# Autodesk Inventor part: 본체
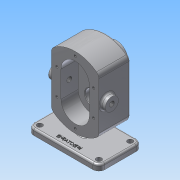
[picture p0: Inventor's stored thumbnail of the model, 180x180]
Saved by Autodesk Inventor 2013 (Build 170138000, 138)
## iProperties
Created: 2019-03
Part Number: 본체
Material: 알루미늄 6061
Document SubType Name: Modeling
Designer: Administrator
Mass: 1191.56 g
Surface Area: 719.273 cm^2
Volume: 439.69 cm^3
Density: 2.71 g/cm^3
Author: Administrator
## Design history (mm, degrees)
sketch "스케치1"
  geometry: L1 (-40, -60)-(40, -60); L2 (40, -44.721)-(40, 44.721); L3 (40, 60)-(-40, 60); L4 (-40, 60)-(-40, -60); L5 (-40, -60)-(40, 60); L6 (40, -60)-(-40, 60); A1 r 60 centre (0, 0) between (40, 44.721) and (-40, 44.721); A2 r 60 centre (0, 0) between (-40, -44.721) and (40, -44.721); 3 further points
  constraints: 12 end point, 4 midpoint, 4 point on circle, 2 centre point, 2 coincident, 2 parallel, 2 point on line, 2 tangent, 1 horizontal, 1 perpendicular
  dimensions: "d1" = 80 distance of L3.end L3.start; "d3" = 60 radius of A1; "d4" = 60 radius of A2; "d5" = 89.44272 distance of L2.start L2.end; "d6" = 80 distance between parallel lines of L4 L2; "d7" = 40 distance from line of L2 point (0, 0)
extrude "돌출1" new body sketch "스케치1" distance "d8" = 53; taper "d9" = 0 deg
fillet "모깎기1" dims "d10" = 10
sketch "스케치2"
  geometry: L1 (-40, 40)-(-40, -40) reference; L2 (0, 0)-(0, 22); L3 (0, 0)-(0, -22); L4 (-24, 22)-(-24, -22); L5 (24, 22)-(24, -22); A1 r 60 centre (0, 0) between (36, 48) and (-36, 48) reference; A2 r 24 centre (0, 22) between (24, 22) and (9.592, 0); A3 r 24 centre (0, -22) between (-24, -22) and (-9.592, 0)
  constraints: 8 end point, 8 point on circle, 3 parallel, 2 centre point, 2 coincident, 2 tangent, 1 collinear
  dimensions: "d11" = 22 distance of L2.start L2.end; "d12" = 48 diameter of A2; "d13" = 22 distance of L2.start L3.end; "d14" = 48 diameter of A3
extrude "돌출2" cut sketch "스케치2" distance "d15" = 29; taper "d16" = 0 deg
sketch "스케치3"
  geometry: C1 r 12.5 at (0, -22); C2 r 12.5 at (0, 22); A1 r 24 centre (0, -22) between (-24, -22) and (24, -22) reference; A2 r 24 centre (0, 22) between (24, 22) and (-24, 22) reference; 1 further point
  constraints: 2 centre point, 2 coincident
  dimensions: "d17" = 25 diameter of C1; "d18" = 25 diameter of C2
extrude "돌출3" cut sketch "스케치3" distance "d19" = 15; taper "d20" = 0 deg
sketch "스케치4"
  geometry: L1 (-40, -40)-(-40, 40) reference; L2 (0, 0)-(0, 22); C1 r 19 at (0, 22); A1 r 60 centre (0, 0) between (-36, -48) and (36, -48) reference
  constraints: 2 end point, 1 centre point, 1 coincident, 1 parallel
  dimensions: "d21" = 22 distance of L2.start L2.end; "d22" = 38 diameter of C1
extrude "돌출4" join sketch "스케치4" distance "d23" = 17; taper "d24" = 0 deg
sketch "스케치5"
  geometry: C1 r 19 at (0, 0) reference; 2 further points
  constraints: 1 coincident
hole "구멍1" sketch "스케치5" at (0, 0) diameter "d25" = 17; stored, may be unused: countersink angle "d29" = 90 deg, drill point angle "d31" = 118 deg; dims "d26" = 6, "d27" = 28, "d28" = 7.3, "d30" = 8
sketch "스케치6"
  geometry: L1 (46, 24)-(46, 53) reference; L2 (46, 53)-(60, 53) reference; L3 (60, 53)-(60, 0) reference; L4 (60, 0)-(41, 0) reference; L5 (41, 0)-(41, -17) reference; L6 (41, -17)-(36, -17) reference; L7 (36, -17)-(36, -9.7) reference; L8 (36, -9.7)-(30.5, -9.7) reference; L9 (30.5, -9.7)-(30.5, 9) reference; L10 (30.5, 9)-(34.5, 9) reference; L11 (34.5, 9)-(34.5, 24) reference; L12 (34.5, 24)-(46, 24) reference; L13 (-46, 53)-(-46, 24) reference; L14 (-46, 24)-(-34.5, 24) reference; L15 (-34.5, 24)-(-34.5, 9) reference; L16 (-34.5, 9)-(-9.5, 9) reference; L17 (-9.5, 9)-(-9.5, 24) reference; L18 (-9.5, 24)-(9.5, 24) reference; L19 (9.5, 24)-(9.5, 9) reference; L20 (9.5, 9)-(13.5, 9) reference; L21 (13.5, 9)-(13.5, -9.7) reference; L22 (13.5, -9.7)-(8, -9.7) reference; L23 (8, -9.7)-(8, -17) reference; L24 (8, -17)-(3, -17) reference; L25 (3, -17)-(3, 0) reference; L26 (3, 0)-(-60, 0) reference; L27 (-60, 0)-(-60, 53) reference; L28 (-60, 53)-(-46, 53) reference; L29 (36, -9.7)-(36, -17) reference; L30 (3, -17)-(41, -17) reference; L31 (8, -9.7)-(8, -17) reference; L32 (36, -17)-(36, -16.3); L33 (36, -16.3)-(36.404, -17); L34 (41, 0)-(3, 0) reference; L35 (22, 0)-(22, -17); L36 (36, -16.3)-(22, -16.3); L37 (22, -17)-(36.404, -17); 1 further point
  constraints: 10 end point, 3 point on line, 2 midpoint, 1 parallel, 1 perpendicular
  dimensions: "d32" = 0.7 distance of L29.end L32.end; "d33" = 30 deg angle of L32 L33
revolve "회전1" sketch "스케치6" stored, may be unused: angle "d34" = 90 deg
fillet "모깎기2" dims "d35" = 0.5
chamfer "모따기1" distance "d36" = 1; stored, may be unused: second distance "d37" = 2, angle "d38" = 45 deg
sketch "스케치7"
  geometry: L1 (-53, 0)-(-53, 80) reference; C1 r 11 at (-39, 40); 1 further point
  constraints: 1 centre point
  dimensions: "d40" = 22 diameter of C1; "d86" = 14 distance from line of C1.centre L1
extrude "돌출5" join sketch "스케치7" distance "d41" = 8; taper "d42" = 0 deg
sketch "스케치8"
  geometry: C1 r 11 at (0, 0) reference; 2 further points
  constraints: 1 coincident
hole "구멍2" sketch "스케치8" at (0, 0) diameter "d43" = 8.376; stored, may be unused: countersink angle "d47" = 90 deg, drill point angle "d49" = 118 deg; dims "d44" = 6, "d45" = 28, "d46" = 7.3, "d48" = 8
fillet "모깎기3" dims "d50" = 3
sketch "스케치9"
  geometry: A1 r 24 centre (0, 22) between (24, 22) and (-24, 22) reference; A2 r 24 centre (0, -22) between (-24, -22) and (24, -22) reference; A3 r 60 centre (0, 0) between (-36, -48) and (36, -48) reference; A4 r 60 centre (0, 0) between (36, 48) and (-36, 48) reference; A5 r 31 centre (0, 22) between (0, 53) and (-31, 22); A6 r 31 centre (0, -22) between (0, -53) and (31, -22); 2 further points
  constraints: 6 point on circle, 3 horizontal alignment, 3 vertical alignment, 2 centre point, 2 coincident
  dimensions: "d51" = 62 diameter of A5; "d52" = 62 diameter of A6; "d53" = 62 distance of A6.end point (-31, -22)
hole "구멍3" sketch "스케치9" at (0, 53), (-31, 22), (31, 22), (0, -53), (31, -22), (-31, -22) diameter "d54" = 4.134; stored, may be unused: countersink angle "d58" = 90 deg, drill point angle "d60" = 118 deg; dims "d55" = 10, "d56" = 28, "d57" = 7.3, "d59" = 12
node "작업 평면1"
sketch "스케치10"
  geometry: L1 (36, 53)-(-36, 53) reference; L2 (-60, 0)-(60, 0); L3 (60, 0)-(60, 73); L4 (60, 73)-(-60, 73); L5 (-60, 73)-(-60, 0); L6 (40, 0)-(40, 53) reference; L7 (-40, 53)-(-40, 0) reference; 2 further points
  constraints: 8 end point, 2 parallel, 1 coincident, 1 horizontal, 1 midpoint, 1 perpendicular
  dimensions: "d62" = 120 distance of L4.end L3.end; "d63" = 73 distance of L3.end L2.end
extrude "돌출6" join sketch "스케치10" distance "d64" = 10; taper "d65" = 0 deg
fillet "모깎기4" dims "d66" = 10
sketch "스케치11"
  geometry: A1 r 10 centre (-50, -10) between (-50, 0) and (-60, -10) reference; A2 r 10 centre (-50, -63) between (-60, -63) and (-50, -73) reference; A3 r 10 centre (50, -63) between (50, -73) and (60, -63) reference; A4 r 10 centre (50, -10) between (60, -10) and (50, 0) reference; 5 further points
  constraints: 4 coincident
hole "구멍4" sketch "스케치11" at (-50, -63), (-50, -10), (50, -10), (50, -63) diameter "d67" = 9; stored, may be unused: countersink angle "d71" = 90 deg, drill point angle "d73" = 118 deg; dims "d68" = 10, "d69" = 28, "d70" = 7.3, "d72" = 12
sketch "스케치12"
  geometry: L1 (-78, 0)-(-78, 73) reference; L2 (-78, 73)-(-68, 73) reference; L3 (-68, 73)-(-68, 0) reference; L4 (-68, 0)-(-78, 0) reference; L5 (3, -17)-(3, 0) reference; L6 (3, 0)-(-60, 0) reference; L7 (-60, 0)-(-60, 53) reference; L8 (-60, 53)-(-55.067, 53) reference; L9 (-55.067, 53)-(-55.067, 41) reference; L10 (-55.067, 41)-(-53, 39.758) reference; L11 (-53, 39.758)-(-50.933, 41) reference; L12 (-50.933, 41)-(-50.933, 53) reference; L13 (-50.933, 53)-(-46, 53) reference; L14 (-46, 53)-(-46, 24) reference; L15 (-46, 24)-(-35.5, 24) reference; L16 (-35.5, 24)-(-34.5, 23) reference; L17 (-34.5, 23)-(-34.5, 9) reference; L18 (-34.5, 9)-(-9.5, 9) reference; L19 (-9.5, 9)-(-9.5, 23) reference; L20 (-9.5, 23)-(-8.5, 24) reference; L21 (-8.5, 24)-(8.5, 24) reference; L22 (8.5, 24)-(9.5, 23) reference; L23 (9.5, 23)-(9.5, 9) reference; L24 (9.5, 9)-(13.5, 9) reference; L25 (13.5, 9)-(13.5, -9.7) reference; L26 (13.5, -9.7)-(8.5, -9.7) reference; L27 (8, -10.2)-(8, -16.3) reference; L28 (8, -16.3)-(7.596, -17) reference; L29 (7.596, -17)-(3, -17) reference; L30 (41, 0)-(41, -17) reference; L31 (41, -17)-(36.404, -17) reference; L32 (36.404, -17)-(36, -16.3) reference; L33 (36, -16.3)-(36, -10.2) reference; L34 (35.5, -9.7)-(30.5, -9.7) reference; L35 (30.5, -9.7)-(30.5, 9) reference; L36 (30.5, 9)-(34.5, 9) reference; L37 (34.5, 9)-(34.5, 23) reference; L38 (34.5, 23)-(35.5, 24) reference; L39 (35.5, 24)-(46, 24) reference; L40 (46, 24)-(46, 53) reference; L41 (46, 53)-(50.933, 53) reference; L42 (50.933, 53)-(50.933, 41) reference; L43 (50.933, 41)-(53, 39.758) reference; L44 (53, 39.758)-(55.067, 41) reference; L45 (55.067, 41)-(55.067, 53) reference; L46 (55.067, 53)-(60, 53) reference; L47 (60, 53)-(60, 0) reference; L48 (60, 0)-(41, 0) reference; L49 (-68, 0)-(-56.692, 0); L50 (-56.692, 0)-(-56.692, 43); L51 (-56.692, 43)-(-68, 43); L52 (-68, 43)-(-68, 0); A1 r 0.5 centre (8.5, -10.2) between (8.5, -9.7) and (8, -10.2) reference; A2 r 0.5 centre (35.5, -10.2) between (36, -10.2) and (35.5, -9.7) reference; 1 further point
  constraints: 8 end point, 2 parallel, 1 horizontal, 1 perpendicular
  dimensions: "d74" = 43 distance of L50.end L49.end
extrude "돌출7" join sketch "스케치12" stored distance "d75" = 12; taper "d76" = 0 deg
fillet "모깎기5" dims "d77" = 3
fillet "모깎기6" dims "d78" = 3
fillet "모깎기7" dims "d79" = 3
fillet "모깎기8" dims "d80" = 3
fillet "모깎기9" dims "d81" = 3
sketch "스케치13"
  geometry: L1 (-50, -73)-(50, -73) reference; L2 (-60, -10)-(-60, -63) reference; 2 further points
  constraints: 1 other
  dimensions: "d82" = 10 distance from line of point (0, -63) L1; "d83" = 60 distance from line of point (0, -63) L2
extrude "돌출8" join sketch "스케치13" distance "d84" = 0.5; taper "d85" = 0 deg
node "솔리드1"
mirror "대칭1"
node "절단 모서리 투영1"
node "절단 모서리 투영2"
other parameters: "d61" = -78
